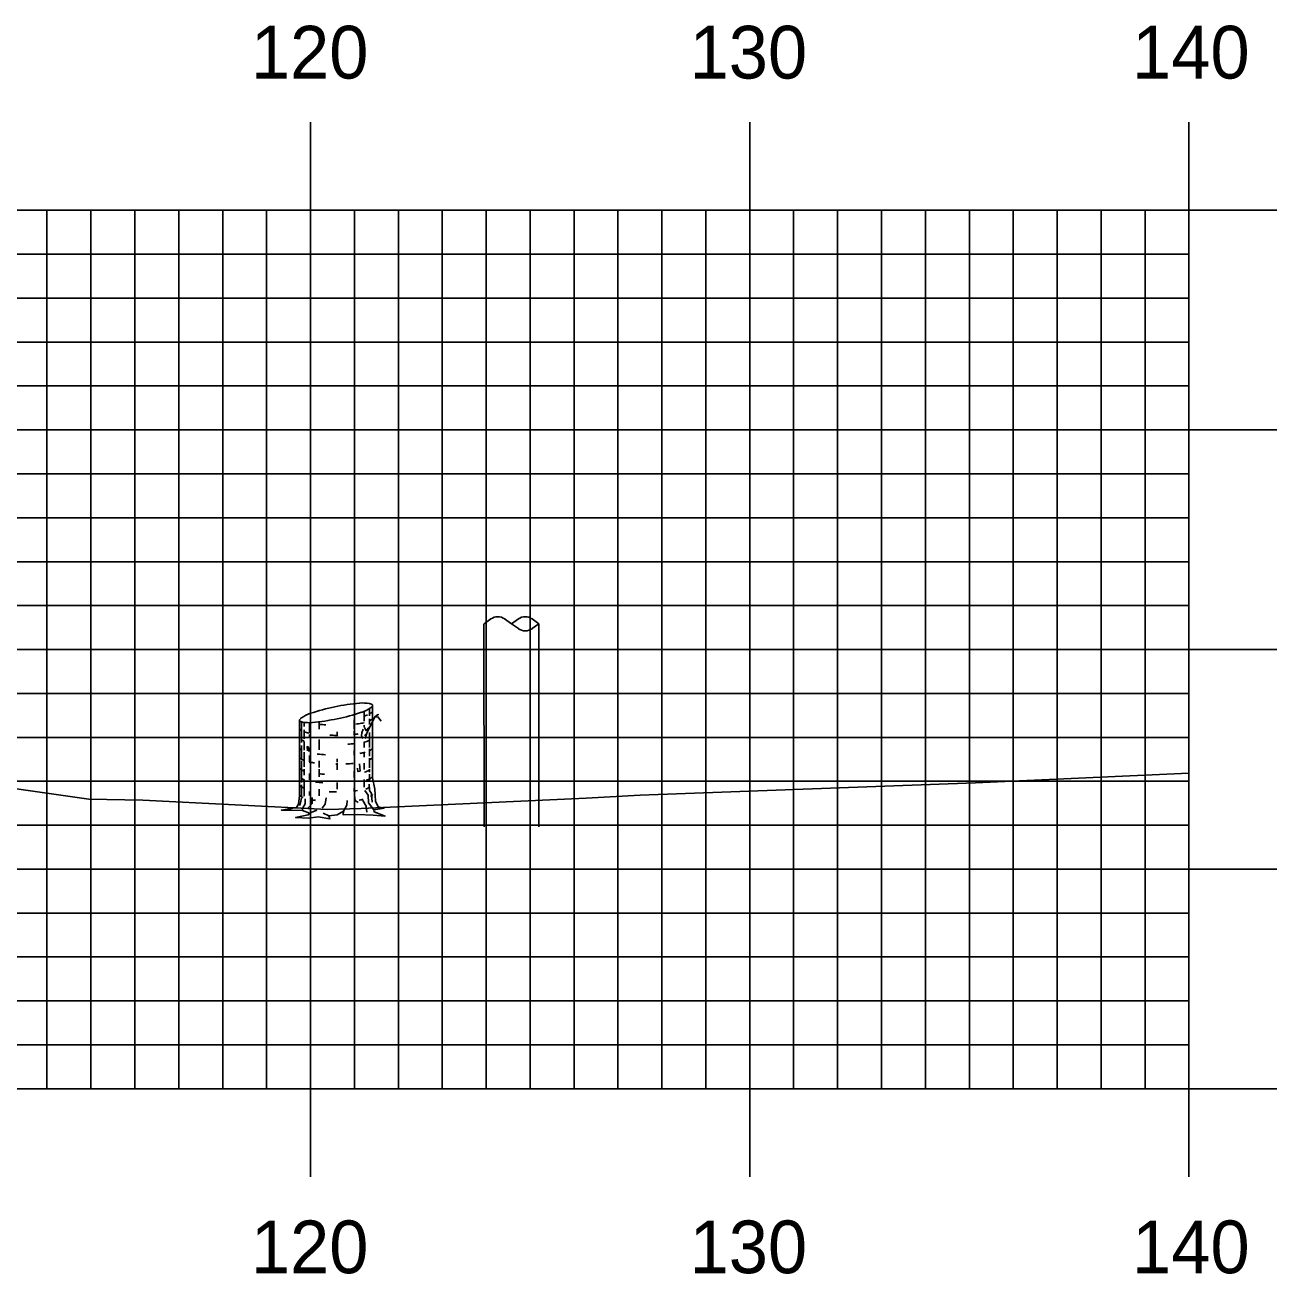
# Model space of a CAD drawing. Extents: x 852087 to 852430, y 366898 to 367118.
# Drawn here: x 852366.03 to 852394.54, y 367003.94 to 367032.38 of the extents above; entities that cross this region are included whole.
import ezdxf

# ---------------------------------------------------------------- set-up
doc = ezdxf.new("R2010")
doc.units = 0
for name, color, linetype in [('H_V ANNOTATION', 7, 'Continuous'), ('MAJOR', 7, 'Continuous'), ('MINOR', 7, 'Continuous'), ('S_Roadway_Centerline', 7, 'Continuous'), ('S_Trees_Conifer_Pay', 7, 'Continuous'), ('S_Utilities_Pole_Power', 7, 'Continuous')]:
    doc.layers.add(name, color=color, linetype=linetype)

msp = doc.modelspace()

# ---------------------------------------------------------------- linework, layer by layer
at = {"layer": 'MAJOR'}
for p, q in [((852372.531, 367030.165), (852372.531, 367028.161)), ((852382.531, 367030.165), (852382.531, 367028.161)), ((852392.531, 367030.165), (852392.531, 367028.161)), ((852112.531, 367028.161), (852392.531, 367028.161)), ((852112.531, 367028.161), (852392.531, 367028.161)), ((852372.531, 367008.161), (852372.531, 367028.161)), ((852382.531, 367008.161), (852382.531, 367028.161)), ((852394.535, 367028.161), (852390.527, 367028.161)), ((852392.531, 367008.161), (852392.531, 367028.161)), ((852392.531, 367008.161), (852392.531, 367028.161)), ((852112.531, 367023.161), (852392.531, 367023.161)), ((852394.535, 367023.161), (852390.527, 367023.161)), ((852112.531, 367018.161), (852392.531, 367018.161)), ((852394.535, 367018.161), (852390.527, 367018.161)), ((852112.531, 367013.161), (852392.531, 367013.161)), ((852394.535, 367013.161), (852390.527, 367013.161)), ((852112.531, 367008.161), (852392.531, 367008.161)), ((852112.531, 367008.161), (852392.531, 367008.161)), ((852372.531, 367006.157), (852372.531, 367008.161)), ((852382.531, 367006.157), (852382.531, 367008.161)), ((852394.535, 367008.161), (852390.527, 367008.161)), ((852392.531, 367006.157), (852392.531, 367008.161))]:
    msp.add_line(p, q, dxfattribs=at)
at = {"layer": 'MINOR'}
for p, q in [((852366.531, 367008.161), (852366.531, 367028.161)), ((852367.531, 367008.161), (852367.531, 367028.161)), ((852368.531, 367008.161), (852368.531, 367028.161)), ((852369.531, 367008.161), (852369.531, 367028.161)), ((852370.531, 367008.161), (852370.531, 367028.161)), ((852371.531, 367008.161), (852371.531, 367028.161)), ((852373.531, 367008.161), (852373.531, 367028.161)), ((852374.531, 367008.161), (852374.531, 367028.161)), ((852375.531, 367008.161), (852375.531, 367028.161)), ((852376.531, 367008.161), (852376.531, 367028.161)), ((852377.531, 367008.161), (852377.531, 367028.161)), ((852378.531, 367008.161), (852378.531, 367028.161)), ((852379.531, 367008.161), (852379.531, 367028.161)), ((852380.531, 367008.161), (852380.531, 367028.161)), ((852381.531, 367008.161), (852381.531, 367028.161)), ((852383.531, 367008.161), (852383.531, 367028.161)), ((852384.531, 367008.161), (852384.531, 367028.161)), ((852385.531, 367008.161), (852385.531, 367028.161)), ((852386.531, 367008.161), (852386.531, 367028.161)), ((852387.531, 367008.161), (852387.531, 367028.161)), ((852388.531, 367008.161), (852388.531, 367028.161)), ((852389.531, 367008.161), (852389.531, 367028.161)), ((852390.531, 367008.161), (852390.531, 367028.161)), ((852391.531, 367008.161), (852391.531, 367028.161)), ((852112.531, 367027.161), (852392.531, 367027.161)), ((852392.531, 367027.161), (852390.527, 367027.161)), ((852112.531, 367026.161), (852392.531, 367026.161)), ((852392.531, 367026.161), (852390.527, 367026.161)), ((852112.531, 367025.161), (852392.531, 367025.161)), ((852392.531, 367025.161), (852390.527, 367025.161)), ((852112.531, 367024.161), (852392.531, 367024.161)), ((852392.531, 367024.161), (852390.527, 367024.161)), ((852112.531, 367022.161), (852392.531, 367022.161)), ((852392.531, 367022.161), (852390.527, 367022.161)), ((852112.531, 367021.161), (852392.531, 367021.161)), ((852392.531, 367021.161), (852390.527, 367021.161)), ((852112.531, 367020.161), (852392.531, 367020.161)), ((852392.531, 367020.161), (852390.527, 367020.161)), ((852112.531, 367019.161), (852392.531, 367019.161)), ((852392.531, 367019.161), (852390.527, 367019.161)), ((852112.531, 367017.161), (852392.531, 367017.161)), ((852392.531, 367017.161), (852390.527, 367017.161)), ((852112.531, 367016.161), (852392.531, 367016.161)), ((852392.531, 367016.161), (852390.527, 367016.161)), ((852112.531, 367015.161), (852392.531, 367015.161)), ((852392.531, 367015.161), (852390.527, 367015.161)), ((852112.531, 367014.161), (852392.531, 367014.161)), ((852392.531, 367014.161), (852390.527, 367014.161)), ((852112.531, 367012.161), (852392.531, 367012.161)), ((852392.531, 367012.161), (852390.527, 367012.161)), ((852112.531, 367011.161), (852392.531, 367011.161)), ((852392.531, 367011.161), (852390.527, 367011.161)), ((852112.531, 367010.161), (852392.531, 367010.161)), ((852392.531, 367010.161), (852390.527, 367010.161)), ((852112.531, 367009.161), (852392.531, 367009.161)), ((852392.531, 367009.161), (852390.527, 367009.161))]:
    msp.add_line(p, q, dxfattribs=at)
at = {"layer": 'S_Roadway_Centerline'}
msp.add_lwpolyline([(852337.113, 367019.027), (852338.043, 367018.914), (852343.951, 367018.056), (852346.148, 367017.712), (852347.762, 367017.504), (852349.813, 367017.28), (852358.822, 367015.994), (852367.486, 367014.752), (852368.716, 367014.728), (852372.915, 367014.517), (852373.687, 367014.538), (852378.806, 367014.779), (852380.034, 367014.842), (852387.67, 367015.125), (852392.531, 367015.348)], dxfattribs=at)
at = {"layer": 'S_Trees_Conifer_Pay'}
for p, q in [((852373.755, 367016.754), (852373.755, 367016.531)), ((852373.872, 367016.815), (852373.872, 367016.652)), ((852373.944, 367015.24), (852373.944, 367016.887)), ((852372.28, 367014.83), (852372.28, 367016.552)), ((852372.327, 367016.515), (852372.327, 367016.044)), ((852372.385, 367016.503), (852372.385, 367016.406)), ((852372.511, 367016.496), (852372.511, 367016.263)), ((852372.731, 367016.516), (852372.731, 367016.348)), ((852373.527, 367016.558), (852373.527, 367016.358)), ((852373.755, 367016.442), (852373.755, 367016.395)), ((852373.872, 367016.585), (852373.872, 367016.457)), ((852372.385, 367016.332), (852372.385, 367016.127)), ((852372.511, 367016.223), (852372.511, 367016.148)), ((852372.731, 367016.111), (852372.731, 367015.874)), ((852373.136, 367016.284), (852373.136, 367016.189)), ((852373.527, 367016.301), (852373.527, 367016.212)), ((852373.812, 367016.259), (852373.761, 367016.2)), ((852373.872, 367016.27), (852373.872, 367015.934)), ((852372.327, 367015.979), (852372.327, 367015.671)), ((852372.385, 367016.07), (852372.385, 367015.87)), ((852372.385, 367015.823), (852372.385, 367015.487)), ((852373.527, 367015.864), (852373.527, 367015.759)), ((852373.755, 367016.06), (852373.755, 367015.928)), ((852373.755, 367015.817), (852373.755, 367015.708)), ((852373.872, 367015.897), (852373.872, 367015.734)), ((852372.327, 367015.624), (852372.327, 367015.131)), ((852372.511, 367015.745), (852372.511, 367015.606)), ((852372.731, 367015.629), (852372.731, 367015.477)), ((852373.136, 367015.671), (852373.136, 367015.597)), ((852373.136, 367015.572), (852373.136, 367015.423)), ((852373.755, 367015.572), (852373.755, 367015.43)), ((852373.872, 367015.687), (852373.872, 367015.471)), ((852372.385, 367015.434), (852372.385, 367015.298)), ((852372.511, 367015.335), (852372.511, 367015.193)), ((852372.731, 367015.434), (852372.731, 367015.261)), ((852373.527, 367015.393), (852373.527, 367015.246)), ((852373.872, 367015.44), (852373.872, 367015.366)), ((852373.872, 367015.325), (852373.872, 367015.152)), ((852372.327, 367015.078), (852372.327, 367014.83)), ((852372.385, 367015.199), (852372.385, 367014.82)), ((852372.731, 367014.983), (852372.731, 367014.83)), ((852373.136, 367015.131), (852373.136, 367014.979)), ((852373.527, 367015.014), (852373.527, 367014.925)), ((852373.755, 367015.203), (852373.755, 367015.03)), ((852372.511, 367014.931), (852372.511, 367014.837)), ((852372.511, 367014.437), (852372.674, 367014.501)), ((852372.948, 367014.373), (852372.822, 367014.437))]:
    msp.add_line(p, q, dxfattribs=at)
for points in [[(852373.761, 367016.385), (852373.798, 367016.311), (852373.845, 367016.368), (852373.903, 367016.437), (852373.995, 367016.63), (852374.059, 367016.677), (852374.09, 367016.684)], [(852373.775, 367016.132), (852373.812, 367016.259), (852373.876, 367016.375), (852373.906, 367016.442), (852373.975, 367016.589)], [(852373.99, 367016.618), (852374.065, 367016.626), (852374.137, 367016.527)], [(852373.727, 367016.348), (852373.696, 367016.263), (852373.693, 367016.196), (852373.723, 367016.132)], [(852372.459, 367015.858), (852372.453, 367015.953), (852372.496, 367015.93), (852372.496, 367015.836)], [(852373.598, 367015.459), (852373.611, 367015.382), (852373.658, 367015.393), (852373.645, 367015.559)], [(852373.944, 367015.24), (852373.995, 367014.979), (852374.011, 367014.705), (852374.069, 367014.58), (852374.205, 367014.549), (852373.975, 367014.511), (852373.975, 367014.511), (852373.981, 367014.464), (852374.228, 367014.37), (852373.954, 367014.386), (852373.598, 367014.406), (852373.277, 367014.396), (852373.283, 367014.479), (852373.135, 367014.396), (852372.948, 367014.373), (852372.972, 367014.305), (852372.704, 367014.349), (852372.484, 367014.322), (852372.191, 367014.339), (852372.48, 367014.396), (852372.511, 367014.437), (852372.348, 367014.495), (852372.111, 367014.505), (852371.87, 367014.505), (852372.212, 367014.563), (852372.254, 367014.643), (852372.28, 367014.83)], [(852373.771, 367014.952), (852373.845, 367014.847), (852373.849, 367014.674), (852373.975, 367014.511)], [(852373.87, 367015.098), (852373.876, 367014.952), (852373.923, 367014.884), (852373.933, 367014.685)], [(852372.328, 367014.783), (852372.307, 367014.705), (852372.286, 367014.61)], [(852372.406, 367014.763), (852372.412, 367014.647), (852372.359, 367014.559), (852372.348, 367014.495)], [(852372.569, 367014.79), (852372.569, 367014.658), (852372.48, 367014.559)], [(852372.795, 367014.549), (852372.862, 367014.643), (852372.889, 367014.783)], [(852373.283, 367014.479), (852373.357, 367014.62), (852373.367, 367014.721)], [(852373.534, 367014.847), (852373.544, 367014.721), (852373.618, 367014.678)], [(852373.812, 367014.458), (852373.798, 367014.596), (852373.723, 367014.725)]]:
    msp.add_lwpolyline(points, dxfattribs=at)
for centre, radius, start, end in [((852374.136, 367011.785), 5.179, 95.3794, 101.7194), ((852373.725, 367016.142), 0.802, 79.2194, 95.3794), ((852372.779, 367015.946), 0.802, 108.0594, 124.2194), ((852374.136, 367011.785), 5.179, 101.7194, 108.0594), ((852372.088, 367021.655), 5.179, 281.7194, 288.0594), ((852373.445, 367017.493), 0.802, 288.0594, 304.2194), ((852373.613, 367017.201), 0.571, 284.4317, 292.4132), ((852373.828, 367016.684), 0.251, 71.0501, 79.2194), ((852373.755, 367017.038), 0.251, 304.2194, 312.3887), ((852373.812, 367016.856), 0.172, 300, 311.2506), ((852373.883, 367016.843), 0.0817, 56.7194, 71.0501), ((852373.869, 367016.913), 0.0817, 312.3887, 326.7194), ((852373.885, 367016.773), 0.0624, 311.2506, 330), ((852373.899, 367016.868), 0.0527, 46.923, 56.7194), ((852373.914, 367016.883), 0.0314, 34.2194, 46.923), ((852373.893, 367016.897), 0.0527, 326.7194, 336.5158), ((852373.9, 367016.764), 0.0441, 330, 343.9485), ((852373.918, 367016.886), 0.0264, 23.4074, 34.2194), ((852373.913, 367016.888), 0.0314, 336.5158, 349.2194), ((852373.921, 367016.888), 0.0226, 11.7194, 23.4074), ((852373.921, 367016.888), 0.0226, 0.0315, 11.7194), ((852373.917, 367016.888), 0.0264, 349.2194, 0.0315), ((852373.911, 367016.761), 0.0334, 343.9485, 354.2151), ((852372.312, 367016.374), 0.0334, 163.9485, 180), ((852372.312, 367016.374), 0.0334, 180, 196.0515), ((852372.311, 367016.551), 0.0314, 156.5158, 169.2194), ((852372.306, 367016.552), 0.0264, 169.2194, 180.0315), ((852372.303, 367016.552), 0.0226, 180.0315, 191.7194), ((852372.303, 367016.552), 0.0226, 191.7194, 203.4074), ((852372.322, 367016.377), 0.0441, 196.0515, 210), ((852372.331, 367016.542), 0.0527, 146.7194, 156.5158), ((852372.306, 367016.553), 0.0264, 203.4074, 214.2194), ((852372.31, 367016.556), 0.0314, 214.2194, 226.923), ((852372.355, 367016.526), 0.0817, 132.3887, 146.7194), ((852372.325, 367016.572), 0.0527, 226.923, 236.7194), ((852372.341, 367016.596), 0.0817, 236.7194, 251.0501), ((852372.469, 367016.402), 0.251, 124.2194, 132.3887), ((852372.395, 367016.756), 0.251, 251.0501, 259.2194), ((852372.499, 367017.297), 0.802, 259.2194, 275.3794), ((852372.088, 367021.655), 5.179, 275.3794, 281.7194), ((852373.112, 367020.564), 4.124, 264.6955, 266.7331), ((852373.112, 367020.564), 4.124, 276.238, 278.1032), ((852373.613, 367017.046), 0.571, 278.1032, 284.3667), ((852373.613, 367017.046), 0.571, 297.0237, 300), ((852373.812, 367016.701), 0.172, 300, 311.2506), ((852373.885, 367016.619), 0.0624, 311.2506, 330), ((852373.9, 367016.61), 0.0441, 330, 343.9485), ((852373.911, 367016.607), 0.0334, 343.9485, 354.2151), ((852372.338, 367016.386), 0.0624, 210, 228.7494), ((852372.411, 367016.468), 0.172, 228.7494, 240), ((852372.61, 367016.814), 0.571, 240, 240.3367), ((852372.611, 367016.602), 0.571, 240, 247.0587), ((852372.61, 367016.814), 0.571, 246.8597, 257.9846), ((852373.111, 367020.331), 4.124, 268.0751, 270), ((852373.111, 367020.331), 4.124, 270, 270.3581), ((852373.111, 367020.331), 4.124, 275.7849, 277.0558), ((852373.613, 367016.602), 0.571, 284.4493, 297.0429), ((852373.911, 367016.163), 0.0334, 343.9485, 354.2151), ((852372.312, 367015.927), 0.0334, 163.9485, 180), ((852372.312, 367015.927), 0.0334, 180, 196.0515), ((852372.322, 367015.93), 0.0441, 196.0515, 210), ((852372.338, 367015.939), 0.0624, 210, 228.7494), ((852372.411, 367016.022), 0.172, 228.7494, 240), ((852372.61, 367016.367), 0.571, 240, 240.3367), ((852373.112, 367020.12), 4.124, 273.7052, 275.9504), ((852373.111, 367019.884), 4.124, 277.6125, 278.1032), ((852373.611, 367016.367), 0.571, 278.1032, 286.9296), ((852373.611, 367016.367), 0.571, 297.1896, 300), ((852373.811, 367016.022), 0.172, 300, 311.2506), ((852373.883, 367015.939), 0.0624, 311.2506, 330), ((852373.899, 367015.93), 0.0441, 330, 343.9485), ((852373.909, 367015.927), 0.0334, 343.9485, 354.2151), ((852372.312, 367015.717), 0.0334, 163.9485, 180), ((852372.312, 367015.717), 0.0334, 180, 196.0515), ((852372.322, 367015.72), 0.0441, 196.0515, 210), ((852372.338, 367015.729), 0.0624, 210, 228.7494), ((852372.411, 367015.812), 0.172, 228.7494, 240), ((852372.61, 367016.157), 0.571, 240, 246.8597), ((852372.61, 367016.157), 0.571, 259.2707, 261.8968), ((852373.111, 367019.674), 4.124, 261.8968, 263.1474), ((852373.111, 367019.884), 4.124, 264.081, 266.6676), ((852373.111, 367019.674), 4.124, 270, 270.3581), ((852373.111, 367019.674), 4.124, 273.1493, 275.4569), ((852373.611, 367016.157), 0.571, 297.1896, 300), ((852373.811, 367015.812), 0.172, 300, 311.2506), ((852373.883, 367015.729), 0.0624, 311.2506, 330), ((852373.899, 367015.72), 0.0441, 330, 343.9485), ((852373.909, 367015.717), 0.0334, 343.9485, 354.2151), ((852372.312, 367015.48), 0.0334, 163.9485, 180), ((852372.312, 367015.48), 0.0334, 180, 196.0515), ((852372.312, 367015.283), 0.0334, 163.9485, 180), ((852372.322, 367015.483), 0.0441, 196.0515, 210), ((852372.338, 367015.492), 0.0624, 210, 228.7494), ((852372.411, 367015.575), 0.172, 228.7494, 240), ((852372.61, 367015.92), 0.571, 240, 246.8597), ((852372.599, 367015.728), 0.571, 241.2369, 248.0268), ((852373.111, 367019.438), 4.124, 264.716, 266.3193), ((852373.611, 367015.92), 0.571, 285.3983, 297.1896), ((852373.611, 367015.722), 0.571, 289.2907, 300), ((852373.811, 367015.377), 0.172, 300, 311.2506), ((852373.883, 367015.295), 0.0624, 311.2506, 330), ((852373.899, 367015.285), 0.0441, 330, 343.9485), ((852373.909, 367015.283), 0.0334, 343.9485, 354.2151), ((852372.312, 367015.087), 0.0334, 163.9485, 180), ((852372.312, 367015.087), 0.0334, 180, 196.0515), ((852372.322, 367015.09), 0.0441, 196.0515, 210), ((852372.338, 367015.099), 0.0624, 210, 228.7494), ((852372.411, 367015.182), 0.172, 228.7494, 240), ((852372.61, 367015.527), 0.571, 240, 246.8597), ((852373.111, 367019.24), 4.124, 263.4991, 265.8397), ((852373.111, 367019.044), 4.124, 275.7849, 276.7896), ((852373.611, 367015.527), 0.571, 288.5067, 297.2721), ((852372.312, 367014.867), 0.0334, 163.9485, 180), ((852372.312, 367014.867), 0.0334, 180, 196.0515), ((852372.322, 367014.87), 0.0441, 196.0515, 210), ((852372.338, 367014.879), 0.0624, 210, 228.7494), ((852372.411, 367014.961), 0.172, 228.7494, 240), ((852372.61, 367015.306), 0.571, 240, 244.5314), ((852373.111, 367018.824), 4.124, 262.4438, 263.512), ((852373.111, 367019.044), 4.124, 267.8117, 270), ((852373.111, 367019.044), 4.124, 270, 270.1328), ((852373.111, 367018.824), 4.124, 277.3684, 278.1032), ((852373.611, 367015.306), 0.571, 278.1032, 281.637), ((852373.811, 367014.961), 0.172, 300, 311.2506), ((852373.883, 367014.879), 0.0624, 311.2506, 330), ((852373.899, 367014.87), 0.0441, 330, 343.9485), ((852373.909, 367014.867), 0.0334, 343.9485, 354.2151)]:
    msp.add_arc(centre, radius, start, end, dxfattribs=at)
at = {"layer": 'S_Utilities_Pole_Power'}
for p, q in [((852376.482, 367014.127), (852376.479, 367018.747)), ((852376.482, 367018.747), (852376.639, 367018.857)), ((852376.951, 367018.857), (852377.107, 367018.747)), ((852377.264, 367018.857), (852377.107, 367018.747)), ((852377.107, 367018.747), (852377.264, 367018.636)), ((852377.732, 367018.747), (852377.576, 367018.857)), ((852377.576, 367018.636), (852377.732, 367018.747)), ((852377.732, 367014.127), (852377.729, 367018.747))]:
    msp.add_line(p, q, dxfattribs=at)
for centre, start, end in [((852376.795, 367018.636), 90, 125.2644), ((852376.795, 367018.636), 54.7356, 90), ((852377.42, 367018.636), 90, 125.2644), ((852377.42, 367018.636), 54.7356, 90), ((852377.42, 367018.857), 234.7356, 270), ((852377.42, 367018.857), 270, 305.2644)]:
    msp.add_arc(centre, 0.271, start, end, dxfattribs=at)

# ---------------------------------------------------------------- texts
at = {"layer": 'H_V ANNOTATION'}
for s, p in [('120', (852371.172, 367031.161)), ('130', (852381.161, 367031.161)), ('140', (852391.236, 367031.161)), ('120', (852371.172, 367003.961)), ('130', (852381.161, 367003.961)), ('140', (852391.236, 367003.961))]:
    msp.add_text(s, height=1.2, dxfattribs=at).set_placement(p)

doc.saveas('drawing.dxf')
